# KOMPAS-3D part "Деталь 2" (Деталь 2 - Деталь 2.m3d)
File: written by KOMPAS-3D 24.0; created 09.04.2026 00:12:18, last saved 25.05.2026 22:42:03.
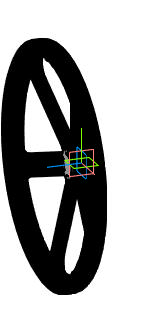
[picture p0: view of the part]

Document properties: Автор: mrdid; Полное имя файла: E:\Работа\Зайцев\АУТСОРС\Даня\GVKN1331N-2W-Fb-R Задвижка шиберная DN.ru Ду400-600 Ру4-6\исходные материалы\DN600\Деталь 2 - Деталь 2.m3d

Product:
- Body: Твердое тело1  | qty 1
    Масса: 4.503579
- Part/product: Деталь 2
    Масса: 4.503579
    additional columns: Типовые

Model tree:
1. Твердое тело1  (labels: Твердое тело1)
2. Масштабирование:1
3. Масштабирование : Твердое тело1
     Масштаб по оси Х = 1; Масштаб по оси Y = 1; Масштаб по оси Z = 1; Коэффициент = 1.66667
